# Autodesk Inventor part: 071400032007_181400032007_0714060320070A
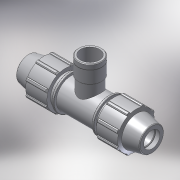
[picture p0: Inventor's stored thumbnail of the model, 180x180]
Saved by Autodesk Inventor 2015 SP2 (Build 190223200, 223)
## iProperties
Created: 2017-02
Part Number: 071400032007_181400032007_0714060320070A
Material: PVC-Piping
Description: PLASSON TEE WITH THREADED FEMALE OFFTAKE 32-3/4"-32
Document SubType Name: Modeling
Designer: KIM
Mass: 92.6774 g
Surface Area: 199.44 cm^2
Volume: 66.1981 cm^3
Density: 1.4 g/cm^3
Appearance: Smooth - White
Author: KIM
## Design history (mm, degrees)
derived "07140.ipt"
feature "Solid1::07140.ipt"
feature "Solid2::07140.ipt"
tag "TaggingFeature1"
body "Solid1"
other parameters: "d2" = 32, "d4" = 7.375, "d5" = 21.24, "d7" = 64, "d11" = 2.95, "d13" = 120 deg, "d14" = 48, "d15" = 12 deg, "d16" = 55.68, "d18" = 1.6, "d19" = 35 deg, "d20" = 17.5 deg, "d21" = 59.52, "d23" = 0, "d25" = 360 deg, "d27" = 1.28, "d33" = 0.64, "d42" = 31.86, "d43" = 1.92, "d46" = 0.96, "d68" = 5.31, "d72" = 51, "d76" = 24.117, "d80" = 0.72351, "d91" = 48, "d93" = 67, "d95" = 28.8, "d112" = 19, "d115" = 30.14625, "d116" = 135 deg, "d117" = 27.73455, "d118" = 177, "d119" = 28.8, "d121" = 0, "d122" = 20.16, "d124" = 0, "d128" = 0, "d129" = 3.2, "d130" = 5.7, "d131" = 0.3, "d132" = 0.3, "d133" = 30.14625, "d_" = 32, "E_" = 64, "A_" = 51, "l_" = 67, "l_2" = 19, "Rp_" = 24.117, "H_" = 177
